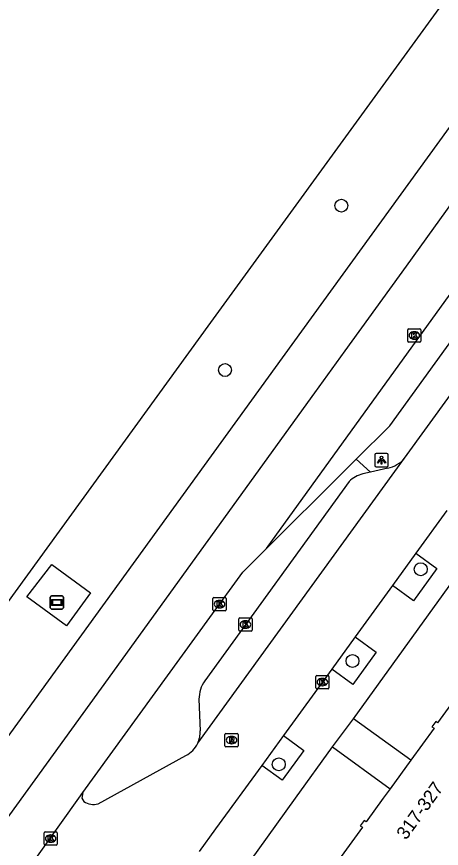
# Model space of a CAD drawing. Extents: x 160107 to 160928, y 382056 to 382918.
# Drawn here: x 160163.8 to 160195.9, y 382246.2 to 382309.1 of the extents above; entities that cross this region are included whole.
import ezdxf

# ---------------------------------------------------------------- set-up
doc = ezdxf.new("R2010")
doc.units = 0
for name, color, linetype in [('IMGEO_Boom', 7, 'Continuous'), ('IMGEO_Kolk', 7, 'Continuous'), ('IMGEO_Lichtpunt', 7, 'Continuous'), ('IMGEO_OVBaan_gesloten', 7, 'Continuous'), ('IMGEO_Pand', 7, 'Continuous'), ('IMGEO_Pand_nummerreeks', 7, 'Continuous'), ('IMGEO_Parkeervlak_open', 7, 'Continuous'), ('IMGEO_Reclamebord', 7, 'Continuous'), ('IMGEO_Rijbaan_lokaal_gesloten', 7, 'Continuous'), ('IMGEO_Rijbaan_lokaal_open', 7, 'Continuous'), ('IMGEO_Rioolput', 7, 'Continuous'), ('IMGEO_Voetpad_open', 7, 'Continuous')]:
    doc.layers.add(name, color=color, linetype=linetype)

msp = doc.modelspace()

# ---------------------------------------------------------------- linework, layer by layer
at = {"layer": 'IMGEO_Boom'}
for centre in [(160188.361, 382294.808), (160179.558, 382282.378), (160194.37, 382267.32), (160189.205, 382260.383), (160183.625, 382252.568)]:
    msp.add_circle(centre, 0.489, dxfattribs=at)
at = {"layer": 'IMGEO_Kolk'}
for p, q in [((160193.458, 382285.494), (160194.31, 382285.494)), ((160193.383, 382284.568), (160193.383, 382285.42)), ((160193.871, 382285.274), (160193.896, 382285.274)), ((160194.384, 382285.42), (160194.384, 382284.568)), ((160194.31, 382284.494), (160193.458, 382284.494)), ((160193.894, 382284.714), (160193.869, 382284.714)), ((160178.645, 382264.252), (160178.645, 382265.104)), ((160178.72, 382265.178), (160179.572, 382265.178)), ((160179.133, 382264.958), (160179.158, 382264.958)), ((160179.646, 382265.104), (160179.646, 382264.252)), ((160179.572, 382264.178), (160178.72, 382264.178)), ((160179.156, 382264.398), (160179.131, 382264.398)), ((160180.601, 382262.714), (160180.601, 382263.566)), ((160180.676, 382263.64), (160181.528, 382263.64)), ((160181.602, 382263.566), (160181.602, 382262.714)), ((160181.112, 382262.86), (160181.087, 382262.86)), ((160181.089, 382263.42), (160181.114, 382263.42)), ((160181.528, 382262.64), (160180.676, 382262.64)), ((160186.424, 382258.362), (160186.424, 382259.214)), ((160186.499, 382259.288), (160187.351, 382259.288)), ((160186.912, 382259.068), (160186.937, 382259.068)), ((160187.425, 382259.214), (160187.425, 382258.362)), ((160186.935, 382258.508), (160186.91, 382258.508)), ((160187.351, 382258.288), (160186.499, 382258.288)), ((160165.86, 382246.53), (160165.86, 382247.382)), ((160165.935, 382247.456), (160166.787, 382247.456)), ((160166.348, 382247.236), (160166.373, 382247.236)), ((160166.861, 382247.382), (160166.861, 382246.53)), ((160166.371, 382246.676), (160166.346, 382246.676)), ((160166.787, 382246.456), (160165.935, 382246.456))]:
    msp.add_line(p, q, dxfattribs=at)
for points in [[(160193.458, 382285.494), (160194.31, 382285.494)], [(160193.383, 382284.568), (160193.383, 382285.42)], [(160193.704, 382285.194), (160193.827, 382285.194), (160193.827, 382285.043), (160193.957, 382285.194), (160194.121, 382285.194), (160193.975, 382285.043), (160194.128, 382284.794), (160193.976, 382284.794), (160193.891, 382284.958), (160193.827, 382284.891), (160193.827, 382284.794), (160193.704, 382284.794), (160193.704, 382285.194)], [(160194.384, 382285.42), (160194.384, 382284.568)], [(160194.31, 382284.494), (160193.458, 382284.494)], [(160178.645, 382264.252), (160178.645, 382265.104)], [(160178.72, 382265.178), (160179.572, 382265.178)], [(160178.966, 382264.878), (160179.089, 382264.878), (160179.089, 382264.727), (160179.219, 382264.878), (160179.383, 382264.878), (160179.237, 382264.727), (160179.39, 382264.478), (160179.238, 382264.478), (160179.153, 382264.642), (160179.089, 382264.575), (160179.089, 382264.478), (160178.966, 382264.478), (160178.966, 382264.878)], [(160179.646, 382265.104), (160179.646, 382264.252)], [(160179.572, 382264.178), (160178.72, 382264.178)], [(160180.601, 382262.714), (160180.601, 382263.566)], [(160180.676, 382263.64), (160181.528, 382263.64)], [(160181.602, 382263.566), (160181.602, 382262.714)], [(160180.922, 382263.34), (160181.045, 382263.34), (160181.045, 382263.189), (160181.175, 382263.34), (160181.339, 382263.34), (160181.193, 382263.189), (160181.346, 382262.94), (160181.194, 382262.94), (160181.109, 382263.104), (160181.045, 382263.037), (160181.045, 382262.94), (160180.922, 382262.94), (160180.922, 382263.34)], [(160181.528, 382262.64), (160180.676, 382262.64)], [(160186.424, 382258.362), (160186.424, 382259.214)], [(160186.499, 382259.288), (160187.351, 382259.288)], [(160187.425, 382259.214), (160187.425, 382258.362)], [(160186.745, 382258.988), (160186.868, 382258.988), (160186.868, 382258.837), (160186.998, 382258.988), (160187.162, 382258.988), (160187.016, 382258.837), (160187.169, 382258.588), (160187.017, 382258.588), (160186.932, 382258.752), (160186.868, 382258.685), (160186.868, 382258.588), (160186.745, 382258.588), (160186.745, 382258.988)], [(160187.351, 382258.288), (160186.499, 382258.288)], [(160165.86, 382246.53), (160165.86, 382247.382)], [(160165.935, 382247.456), (160166.787, 382247.456)], [(160166.181, 382247.156), (160166.304, 382247.156), (160166.304, 382247.005), (160166.434, 382247.156), (160166.598, 382247.156), (160166.452, 382247.005), (160166.605, 382246.756), (160166.453, 382246.756), (160166.368, 382246.92), (160166.304, 382246.853), (160166.304, 382246.756), (160166.181, 382246.756), (160166.181, 382247.156)], [(160166.861, 382247.382), (160166.861, 382246.53)], [(160166.787, 382246.456), (160165.935, 382246.456)]]:
    msp.add_lwpolyline(points, dxfattribs=at)
for centre, start, end in [((160193.46, 382285.418), 91.55205, 178.44795), ((160193.46, 382285.418), 91.55205, 178.44795), ((160194.308, 382285.418), 1.55205, 88.44795), ((160194.308, 382285.418), 1.55205, 88.44795), ((160193.46, 382284.57), 181.55205, 268.44795), ((160193.46, 382284.57), 181.55205, 268.44795), ((160194.308, 382284.57), 271.55205, 358.44795), ((160194.308, 382284.57), 271.55205, 358.44795), ((160178.722, 382265.102), 91.55205, 178.44795), ((160178.722, 382265.102), 91.55205, 178.44795), ((160179.57, 382265.102), 1.55205, 88.44795), ((160179.57, 382265.102), 1.55205, 88.44795), ((160178.722, 382264.254), 181.55205, 268.44795), ((160178.722, 382264.254), 181.55205, 268.44795), ((160179.57, 382264.254), 271.55205, 358.44795), ((160179.57, 382264.254), 271.55205, 358.44795), ((160180.678, 382263.564), 91.55205, 178.44795), ((160180.678, 382263.564), 91.55205, 178.44795), ((160181.526, 382263.564), 1.55205, 88.44795), ((160181.526, 382263.564), 1.55205, 88.44795), ((160180.678, 382262.716), 181.55205, 268.44795), ((160180.678, 382262.716), 181.55205, 268.44795), ((160181.526, 382262.716), 271.55205, 358.44795), ((160181.526, 382262.716), 271.55205, 358.44795), ((160186.501, 382259.212), 91.55205, 178.44795), ((160186.501, 382259.212), 91.55205, 178.44795), ((160187.349, 382259.212), 1.55205, 88.44795), ((160187.349, 382259.212), 1.55205, 88.44795), ((160186.501, 382258.364), 181.55205, 268.44795), ((160186.501, 382258.364), 181.55205, 268.44795), ((160187.349, 382258.364), 271.55205, 358.44795), ((160187.349, 382258.364), 271.55205, 358.44795), ((160165.937, 382247.38), 91.55205, 178.44795), ((160165.937, 382247.38), 91.55205, 178.44795), ((160166.785, 382247.38), 1.55205, 88.44795), ((160166.785, 382247.38), 1.55205, 88.44795), ((160165.937, 382246.532), 181.55205, 268.44795), ((160165.937, 382246.532), 181.55205, 268.44795), ((160166.785, 382246.532), 271.55205, 358.44795), ((160166.785, 382246.532), 271.55205, 358.44795)]:
    msp.add_arc(centre, 0.0765, start, end, dxfattribs=at)
for centre, major_axis, ratio, start_param, end_param in [((160193.87, 382284.994), (-0.387, 0.002), 0.722429, 4.712389, 7.853982), ((160193.895, 382284.994), (-0.39, 0.002), 0.717154, 1.570796, 4.712389), ((160179.132, 382264.678), (-0.387, 0.002), 0.722429, 4.712389, 7.853982), ((160179.157, 382264.678), (-0.39, 0.002), 0.717154, 1.570796, 4.712389), ((160181.088, 382263.14), (-0.387, 0.002), 0.722429, 4.712389, 7.853982), ((160181.113, 382263.14), (-0.39, 0.002), 0.717154, 1.570796, 4.712389), ((160186.911, 382258.788), (-0.387, 0.002), 0.722429, 4.712389, 7.853982), ((160186.936, 382258.788), (-0.39, 0.002), 0.717154, 1.570796, 4.712389), ((160166.347, 382246.956), (-0.387, 0.002), 0.722429, 4.712389, 7.853982), ((160166.372, 382246.956), (-0.39, 0.002), 0.717154, 1.570796, 4.712389)]:
    msp.add_ellipse(centre, major_axis=major_axis, ratio=ratio, start_param=start_param, end_param=end_param, dxfattribs=at)
at = {"layer": 'IMGEO_Lichtpunt'}
for p, q in [((160191.808, 382276.065), (160191, 382276.065)), ((160191.808, 382276.065), (160191, 382276.065)), ((160190.906, 382275.97), (160190.906, 382275.163)), ((160190.906, 382275.97), (160190.906, 382275.163)), ((160191.902, 382275.163), (160191.902, 382275.97)), ((160191.902, 382275.163), (160191.902, 382275.97)), ((160191, 382275.069), (160191.808, 382275.069)), ((160191, 382275.069), (160191.808, 382275.069))]:
    msp.add_line(p, q, dxfattribs=at)
for points in [[(160191.28, 382275.634), (160191.319, 382275.606), (160191.131, 382275.344), (160191.093, 382275.371), (160191.28, 382275.634)], [(160191.382, 382275.586), (160191.429, 382275.586), (160191.429, 382275.264), (160191.382, 382275.264), (160191.382, 382275.586)], [(160191.492, 382275.606), (160191.53, 382275.633), (160191.717, 382275.371), (160191.678, 382275.343), (160191.492, 382275.606)]]:
    msp.add_lwpolyline(points, dxfattribs=at)
msp.add_circle((160191.405, 382275.768), 0.0994, dxfattribs=at)
for centre, start, end in [((160191, 382275.97), 90, 180), ((160191, 382275.97), 90, 180), ((160191.808, 382275.97), 0, 90), ((160191.808, 382275.97), 0, 90), ((160191, 382275.163), 180, 270), ((160191, 382275.163), 180, 270), ((160191.808, 382275.163), 270, 0), ((160191.808, 382275.163), 270, 360)]:
    msp.add_arc(centre, 0.0946, start, end, dxfattribs=at)
at = {"layer": 'IMGEO_OVBaan_gesloten'}
for points in [[(160182.7, 382268.89), (160189.517, 382278.317), (160209.015, 382305.284)], [(160189.486, 382275.629), (160192.026, 382278.151), (160204.91, 382295.921), (160209.015, 382305.284)], [(160182.7, 382268.89), (160188.479, 382274.629), (160189.486, 382275.629)]]:
    msp.add_lwpolyline(points, dxfattribs=at)
at = {"layer": 'IMGEO_Pand'}
for points in [[(160197.864, 382258.755), (160195.65, 382255.7), (160195.507, 382255.804), (160195.22, 382255.408), (160195.374, 382255.296), (160193.632, 382252.892)], [(160193.632, 382252.892), (160192.06, 382250.724)], [(160192.06, 382250.724), (160191.536, 382250), (160190.245, 382248.216), (160190.079, 382248.333), (160189.787, 382247.93), (160189.95, 382247.812), (160187.745, 382244.771)]]:
    msp.add_lwpolyline(points, dxfattribs=at)
at = {"layer": 'IMGEO_Parkeervlak_open'}
for points in [[(160190.566, 382274.667), (160189.982, 382274.536)], [(160188.942, 382273.96), (160178.017, 382258.882)], [(160177.587, 382257.492), (160177.674, 382255.095)]]:
    msp.add_lwpolyline(points, dxfattribs=at)
for centre, radius, start, end in [((160190.618, 382272.161), 2.458, 104.98775, 132.97167), ((160180.006, 382257.505), 2.419, 145.31028, 180.31055), ((160175.693, 382255.003), 1.983, 334.83859, 2.65941)]:
    msp.add_arc(centre, radius, start, end, dxfattribs=at)
at = {"layer": 'IMGEO_Reclamebord'}
for p, q in [((160166.331, 382264.41), (160166.331, 382265.21)), ((160166.331, 382265.21), (160166.331, 382264.41)), ((160166.431, 382265.31), (160167.221, 382265.31)), ((160167.221, 382265.31), (160166.431, 382265.31)), ((160167.321, 382265.21), (160167.321, 382264.41)), ((160167.321, 382264.41), (160167.321, 382265.21)), ((160167.221, 382264.31), (160166.431, 382264.31)), ((160166.431, 382264.31), (160167.221, 382264.31))]:
    msp.add_line(p, q, dxfattribs=at)
for points in [[(160166.432, 382265.042), (160167.22, 382265.042), (160167.22, 382264.578), (160166.432, 382264.578), (160166.432, 382265.042)], [(160166.497, 382264.977), (160166.497, 382264.643), (160167.155, 382264.643), (160167.155, 382264.977), (160166.497, 382264.977)]]:
    msp.add_lwpolyline(points, dxfattribs=at)
for centre, start, end in [((160166.431, 382265.21), 90, 180), ((160166.431, 382265.21), 90, 180), ((160167.221, 382265.21), 0, 90), ((160167.221, 382265.21), 360, 90), ((160166.431, 382264.41), 180, 270), ((160166.431, 382264.41), 180, 270), ((160167.221, 382264.41), 270, 0), ((160167.221, 382264.41), 270, 0)]:
    msp.add_arc(centre, 0.1, start, end, dxfattribs=at)
at = {"layer": 'IMGEO_Rijbaan_lokaal_gesloten'}
for points in [[(160152.266, 382250), (160153.158, 382251.113), (160178.492, 382285.961), (160207.787, 382326.257), (160212.852, 382333.289), (160218.035, 382340.57), (160223.233, 382348.042), (160228.076, 382354.969), (160232.786, 382361.903), (160237.958, 382369.491), (160241.999, 382375.5), (160249.716, 382387.135)], [(160157.826, 382247.361), (160159.74, 382250), (160183.373, 382282.577), (160223.206, 382337.486)], [(160207.086, 382309.322), (160202.467, 382302.938), (160197.852, 382296.6), (160193.26, 382290.223), (160188.631, 382283.837), (160186.317, 382280.652), (160170.172, 382258.34), (160160.981, 382245.655), (160158.719, 382242.359), (160156.582, 382238.916), (160154.79, 382235.339), (160153.185, 382231.678), (160151.754, 382227.946), (160150.523, 382224.115), (160149.528, 382220.211), (160148.783, 382216.257), (160148.254, 382212.316), (160148.094, 382210.855)], [(160168.792, 382250.438), (160178.408, 382263.675), (160180.903, 382267.105), (160182.7, 382268.89)], [(160163.003, 382242.288), (160168.481, 382250), (160168.792, 382250.438)]]:
    msp.add_lwpolyline(points, dxfattribs=at)
at = {"layer": 'IMGEO_Rijbaan_lokaal_open'}
for points in [[(160193.147, 382275.71), (160210.95, 382300.202)], [(160177.488, 382254.16), (160193.147, 382275.71)], [(160196.334, 382271.765), (160193.997, 382268.54)], [(160193.997, 382268.54), (160192.224, 382266.094)], [(160192.224, 382266.094), (160189.4, 382262.198)], [(160189.4, 382262.198), (160187.64, 382259.769)], [(160187.64, 382259.769), (160183.979, 382254.741)], [(160183.979, 382254.741), (160182.335, 382252.486)], [(160169.951, 382249.584), (160176.593, 382253.24)], [(160182.335, 382252.486), (160178.833, 382247.682), (160177.591, 382245.978)], [(160168.792, 382250.438), (160168.719, 382250), (160168.86, 382249.748)]]:
    msp.add_lwpolyline(points, dxfattribs=at)
for centre, radius, start, end in [((160175.711, 382254.994), 1.963, 296.71029, 334.86801), ((160169.602, 382250.976), 1.435, 238.84818, 284.05434)]:
    msp.add_arc(centre, radius, start, end, dxfattribs=at)
at = {"layer": 'IMGEO_Rioolput'}
for p, q in [((160179.553, 382253.978), (160179.553, 382254.83)), ((160179.628, 382254.904), (160180.48, 382254.904)), ((160180.041, 382254.684), (160180.066, 382254.684)), ((160180.554, 382254.83), (160180.554, 382253.978)), ((160180.064, 382254.124), (160180.039, 382254.124)), ((160180.48, 382253.904), (160179.628, 382253.904))]:
    msp.add_line(p, q, dxfattribs=at)
for points in [[(160179.553, 382253.978), (160179.553, 382254.83)], [(160179.628, 382254.904), (160180.48, 382254.904)], [(160180.554, 382254.83), (160180.554, 382253.978)], [(160180.142, 382254.602), (160179.89, 382254.604), (160179.89, 382254.204)], [(160179.89, 382254.204), (160180.014, 382254.204), (160180.014, 382254.366), (160180.025, 382254.366)], [(160180.068, 382254.523), (160180.014, 382254.523), (160180.014, 382254.442)], [(160180.014, 382254.442), (160180.066, 382254.442)], [(160180.072, 382254.337), (160180.143, 382254.204), (160180.283, 382254.204), (160180.218, 382254.33)], [(160180.48, 382253.904), (160179.628, 382253.904)]]:
    msp.add_lwpolyline(points, dxfattribs=at)
for centre, radius, start, end in [((160179.63, 382254.828), 0.0765, 91.55205, 178.44795), ((160179.63, 382254.828), 0.0765, 91.55205, 178.44795), ((160180.478, 382254.828), 0.0765, 1.55205, 88.44795), ((160180.478, 382254.828), 0.0765, 1.55205, 88.44795), ((160180.024, 382254.313), 0.0533, 26.02933, 88.69889), ((160180.05, 382254.631), 0.19, 274.7715, 282.96867), ((160180.074, 382254.427), 0.0964, 77.00612, 93.18647), ((160180.088, 382254.484), 0.0378, 276.66336, 79.67722), ((160180.141, 382254.492), 0.109, 350.36119, 89.41601), ((160180.139, 382254.492), 0.112, 277.58423, 350.98172), ((160180.123, 382254.277), 0.108, 29.51342, 73.79051), ((160179.63, 382253.98), 0.0765, 181.55205, 268.44795), ((160179.63, 382253.98), 0.0765, 181.55205, 268.44795), ((160180.478, 382253.98), 0.0765, 271.55205, 358.44795), ((160180.478, 382253.98), 0.0765, 271.55205, 358.44795)]:
    msp.add_arc(centre, radius, start, end, dxfattribs=at)
for centre, major_axis, ratio, start_param, end_param in [((160180.04, 382254.404), (-0.387, 0.002), 0.722429, 4.712389, 7.853982), ((160180.065, 382254.404), (-0.39, 0.002), 0.717154, 1.570796, 4.712389)]:
    msp.add_ellipse(centre, major_axis=major_axis, ratio=ratio, start_param=start_param, end_param=end_param, dxfattribs=at)
at = {"layer": 'IMGEO_Voetpad_open'}
for points in [[(160190.566, 382274.667), (160189.486, 382275.629)], [(160191.875, 382274.96), (160190.566, 382274.667)], [(160193.997, 382268.54), (160195.6, 382267.372), (160193.82, 382264.93), (160192.224, 382266.094)], [(160189.276, 382256.014), (160197.953, 382268.028)], [(160166.448, 382267.665), (160169.378, 382265.539), (160167.55, 382263.043), (160164.563, 382265.231), (160166.448, 382267.665)], [(160189.4, 382262.198), (160190.995, 382261.049), (160189.241, 382258.615), (160187.64, 382259.769)], [(160187.697, 382253.897), (160189.276, 382256.014)], [(160193.632, 382252.892), (160189.276, 382256.014)], [(160183.979, 382254.741), (160185.514, 382253.621), (160183.87, 382251.367), (160182.335, 382252.486)], [(160179.268, 382242.193), (160182.063, 382246.074), (160184.89, 382250), (160187.697, 382253.897)], [(160187.697, 382253.897), (160192.06, 382250.724)]]:
    msp.add_lwpolyline(points, dxfattribs=at)
msp.add_arc((160191.385, 382277.245), 2.337, 282.10558, 318.94355, dxfattribs=at)

# ---------------------------------------------------------------- texts
at = {"layer": 'IMGEO_Pand_nummerreeks'}
msp.add_text('317-327', height=1, rotation=54.1104, dxfattribs=at).set_placement((160193.259, 382246.795))

doc.saveas('drawing.dxf')
